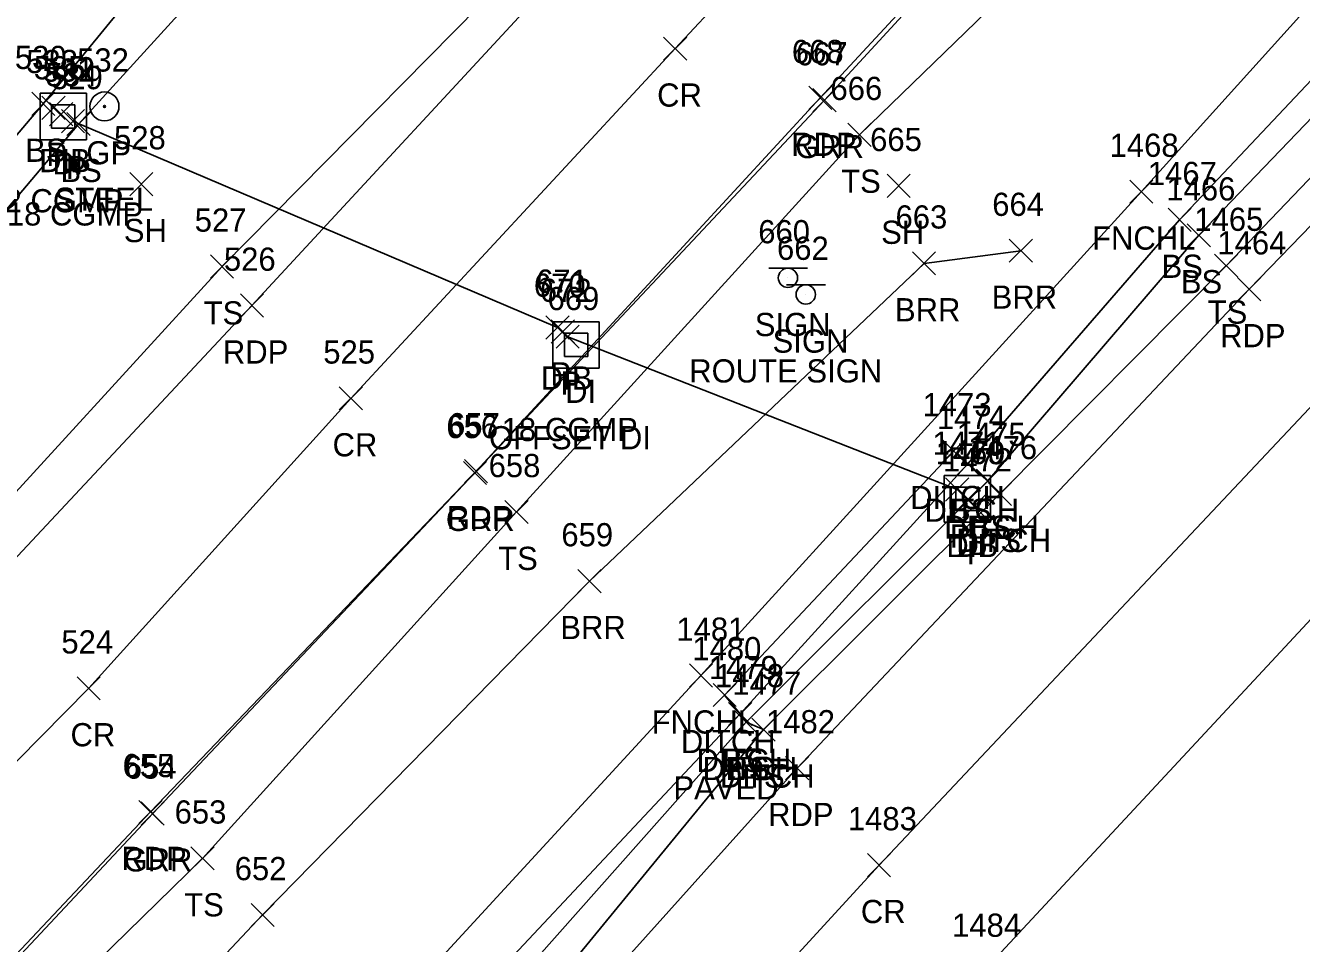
# Model space of a CAD drawing. Extents: x 1688195 to 1692013, y 424605 to 441234.
# Drawn here: x 1691404.7 to 1691514.7, y 438896.5 to 438975.6 of the extents above; entities that cross this region are included whole.
import ezdxf

# ---------------------------------------------------------------- set-up
doc = ezdxf.new("R2010")
doc.units = 0
for name, color, linetype in [('D_A', 7, 'Continuous'), ('D_C', 7, 'Continuous'), ('D_I', 7, 'Continuous'), ('D_TIC', 7, 'Continuous'), ('DCP', 7, 'Continuous'), ('DD', 7, 'Continuous'), ('DS', 7, 'Continuous'), ('L_A', 7, 'Continuous'), ('L_I', 7, 'Continuous'), ('L_TIC', 7, 'Continuous'), ('LABL', 7, 'Continuous'), ('LELB', 7, 'Continuous'), ('LFNC', 7, 'Continuous'), ('P_A', 7, 'Continuous'), ('P_I', 7, 'Continuous'), ('P_TIC', 7, 'Continuous'), ('PET', 7, 'Continuous'), ('PRC', 7, 'Continuous'), ('R_A', 7, 'Continuous'), ('R_C', 7, 'Continuous'), ('R_I', 7, 'Continuous'), ('R_TIC', 7, 'Continuous'), ('RGP', 7, 'Continuous'), ('RGR', 7, 'Continuous'), ('S_A', 7, 'Continuous'), ('S_C', 7, 'Continuous'), ('S_I', 7, 'Continuous'), ('SSGN', 7, 'Continuous')]:
    doc.layers.add(name, color=color, linetype=linetype)

msp = doc.modelspace()

# ---------------------------------------------------------------- linework, layer by layer
at = {"layer": 'D_TIC'}
for points in [[(1691406.08, 438967.48), (1691408.08, 438969.48)], [(1691408.08, 438967.48), (1691406.08, 438969.48)], [(1691406.74, 438966.94), (1691408.74, 438968.94)], [(1691408.74, 438966.94), (1691406.74, 438968.94)], [(1691407.75, 438966.34), (1691409.75, 438968.34)], [(1691409.75, 438966.34), (1691407.75, 438968.34)], [(1691449.54, 438948.55), (1691451.54, 438950.55)], [(1691451.54, 438948.55), (1691449.54, 438950.55)], [(1691449.99, 438948.2), (1691451.99, 438950.2)], [(1691451.99, 438948.2), (1691449.99, 438950.2)], [(1691450.42, 438947.76), (1691452.42, 438949.76)], [(1691452.42, 438947.76), (1691450.42, 438949.76)], [(1691483.71, 438937.9), (1691485.71, 438939.9)], [(1691485.71, 438937.9), (1691483.71, 438939.9)], [(1691483.71, 438937.9), (1691485.71, 438939.9)], [(1691485.71, 438937.9), (1691483.71, 438939.9)], [(1691484.94, 438936.8), (1691486.94, 438938.8)], [(1691486.94, 438936.8), (1691484.94, 438938.8)], [(1691484, 438934.58), (1691486, 438936.58)], [(1691486, 438934.58), (1691484, 438936.58)], [(1691486.66, 438935.34), (1691488.66, 438937.34)], [(1691488.66, 438935.34), (1691486.66, 438937.34)], [(1691484.96, 438933.76), (1691486.96, 438935.76)], [(1691486.96, 438933.76), (1691484.96, 438935.76)], [(1691487.69, 438934.2), (1691489.69, 438936.2)], [(1691489.69, 438934.2), (1691487.69, 438936.2)], [(1691485.47, 438933.15), (1691487.47, 438935.15)], [(1691487.47, 438933.15), (1691485.47, 438935.15)], [(1691463.95, 438916.87), (1691465.95, 438918.87)], [(1691465.95, 438916.87), (1691463.95, 438918.87)], [(1691463.95, 438916.87), (1691465.95, 438918.87)], [(1691465.95, 438916.87), (1691463.95, 438918.87)], [(1691465.29, 438915.24), (1691467.29, 438917.24)], [(1691467.29, 438915.24), (1691465.29, 438917.24)], [(1691465.81, 438914.54), (1691467.81, 438916.54)], [(1691467.81, 438914.54), (1691465.81, 438916.54)], [(1691467.3, 438913.89), (1691469.3, 438915.89)], [(1691469.3, 438913.89), (1691467.3, 438915.89)]]:
    msp.add_lwpolyline(points, dxfattribs=at)
at = {"layer": 'DCP'}
for points in [[(1691408.75, 438967.34), (1691450.54, 438949.55)], [(1691451.42, 438948.76), (1691485, 438935.58)]]:
    msp.add_lwpolyline(points, dxfattribs=at)
at = {"layer": 'DD'}
for points in [[(1691484.71, 438938.9), (1691485.94, 438937.8), (1691487.66, 438936.34), (1691488.69, 438935.2), (1691468.3, 438914.89), (1691466.81, 438915.54), (1691466.29, 438916.24), (1691464.95, 438917.87)], [(1691484.71, 438938.9), (1691464.95, 438917.87)]]:
    msp.add_lwpolyline(points, dxfattribs=at)
at = {"layer": 'DS'}
for p, q in [((1691405.91, 438969.74), (1691409.91, 438969.74)), ((1691405.91, 438965.74), (1691405.91, 438969.74)), ((1691409.91, 438969.74), (1691409.91, 438965.74)), ((1691406.91, 438966.74), (1691406.91, 438968.74)), ((1691406.91, 438968.74), (1691408.91, 438968.74)), ((1691408.91, 438968.74), (1691408.91, 438966.74)), ((1691407.91, 438967.74), (1691407.91, 438967.74)), ((1691407.91, 438967.74), (1691407.91, 438967.74)), ((1691408.91, 438966.74), (1691406.91, 438966.74)), ((1691409.91, 438965.74), (1691405.91, 438965.74)), ((1691450.14, 438950.05), (1691454.14, 438950.05)), ((1691450.14, 438946.05), (1691450.14, 438950.05)), ((1691454.14, 438950.05), (1691454.14, 438946.05)), ((1691451.14, 438947.05), (1691451.14, 438949.05)), ((1691451.14, 438949.05), (1691453.14, 438949.05)), ((1691453.14, 438949.05), (1691453.14, 438947.05)), ((1691452.14, 438948.05), (1691452.14, 438948.05)), ((1691452.14, 438948.05), (1691452.14, 438948.05)), ((1691453.14, 438947.05), (1691451.14, 438947.05)), ((1691454.14, 438946.05), (1691450.14, 438946.05)), ((1691483.88, 438936.78), (1691487.88, 438936.78)), ((1691483.88, 438932.78), (1691483.88, 438936.78)), ((1691487.88, 438936.78), (1691487.88, 438932.78)), ((1691484.88, 438933.78), (1691484.88, 438935.78)), ((1691484.88, 438935.78), (1691486.88, 438935.78)), ((1691486.88, 438935.78), (1691486.88, 438933.78)), ((1691485.89, 438934.78), (1691485.89, 438934.78)), ((1691485.89, 438934.78), (1691485.89, 438934.78)), ((1691486.88, 438933.78), (1691484.88, 438933.78)), ((1691487.88, 438932.78), (1691483.88, 438932.78))]:
    msp.add_line(p, q, dxfattribs=at)
at = {"layer": 'L_TIC'}
for points in [[(1691405.19, 438967.83), (1691407.19, 438969.83)], [(1691407.19, 438967.83), (1691405.19, 438969.83)], [(1691408.23, 438966.09), (1691410.23, 438968.09)], [(1691410.23, 438966.09), (1691408.23, 438968.09)], [(1691475.59, 438965.16), (1691477.59, 438967.16)], [(1691477.59, 438965.16), (1691475.59, 438967.16)], [(1691413.65, 438960.91), (1691415.65, 438962.91)], [(1691415.65, 438960.91), (1691413.65, 438962.91)], [(1691478.96, 438960.76), (1691480.96, 438962.76)], [(1691480.96, 438960.76), (1691478.96, 438962.76)], [(1691499.89, 438960.26), (1691501.89, 438962.26)], [(1691501.89, 438960.26), (1691499.89, 438962.26)], [(1691503.19, 438957.83), (1691505.19, 438959.83)], [(1691505.19, 438957.83), (1691503.19, 438959.83)], [(1691504.84, 438956.5), (1691506.84, 438958.5)], [(1691506.84, 438956.5), (1691504.84, 438958.5)], [(1691489.49, 438955.17), (1691491.49, 438957.17)], [(1691491.49, 438955.17), (1691489.49, 438957.17)], [(1691420.61, 438953.81), (1691422.61, 438955.81)], [(1691422.61, 438953.81), (1691420.61, 438955.81)], [(1691481.15, 438954.08), (1691483.15, 438956.08)], [(1691483.15, 438954.08), (1691481.15, 438956.08)], [(1691507.2, 438953.88), (1691509.2, 438955.88)], [(1691509.2, 438953.88), (1691507.2, 438955.88)], [(1691484.94, 438936.8), (1691486.94, 438938.8)], [(1691486.94, 438936.8), (1691484.94, 438938.8)], [(1691486.66, 438935.34), (1691488.66, 438937.34)], [(1691488.66, 438935.34), (1691486.66, 438937.34)], [(1691487.69, 438934.2), (1691489.69, 438936.2)], [(1691489.69, 438934.2), (1691487.69, 438936.2)], [(1691446.01, 438932.65), (1691448.01, 438934.65)], [(1691448.01, 438932.65), (1691446.01, 438934.65)], [(1691452.29, 438926.69), (1691454.29, 438928.69)], [(1691454.29, 438926.69), (1691452.29, 438928.69)], [(1691461.91, 438918.55), (1691463.91, 438920.55)], [(1691463.91, 438918.55), (1691461.91, 438920.55)], [(1691465.29, 438915.24), (1691467.29, 438917.24)], [(1691467.29, 438915.24), (1691465.29, 438917.24)], [(1691465.81, 438914.54), (1691467.81, 438916.54)], [(1691467.81, 438914.54), (1691465.81, 438916.54)], [(1691467.3, 438913.89), (1691469.3, 438915.89)], [(1691469.3, 438913.89), (1691467.3, 438915.89)], [(1691418.93, 438902.79), (1691420.93, 438904.79)], [(1691420.93, 438902.79), (1691418.93, 438904.79)], [(1691424.11, 438897.91), (1691426.11, 438899.91)], [(1691426.11, 438897.91), (1691424.11, 438899.91)]]:
    msp.add_lwpolyline(points, dxfattribs=at)
at = {"layer": 'LABL'}
msp.add_lwpolyline([(1691400.95, 438873.28), (1691425.11, 438898.91), (1691453.29, 438927.69), (1691482.15, 438955.08), (1691490.49, 438956.17)], dxfattribs=at)
at = {"layer": 'LELB'}
for points in [[(1691372.73, 438902.64), (1691398.57, 438929.63), (1691421.61, 438954.81), (1691450.5, 438984.08), (1691477.46, 439013.34), (1691508.26, 439046.52), (1691540.85, 439082.44), (1691568.31, 439110.72), (1691593.69, 439141.21), (1691622.93, 439171.73), (1691652.84, 439206.76), (1691674.71, 439229.19), (1691701.22, 439256.48), (1691710.89, 439279.75), (1691723.95, 439307.99), (1691712.17, 439332.07), (1691693.94, 439358.26), (1691684, 439373.02)], [(1691358.65, 438915.95), (1691383.88, 438942.54), (1691406.19, 438968.83), (1691432.09, 439000.43), (1691458.78, 439030.79), (1691488.91, 439063.66), (1691516.55, 439102.83), (1691546.52, 439127.21), (1691571.44, 439162.09), (1691585.36, 439179.75), (1691595.61, 439189.84), (1691598.8, 439192.56), (1691623.09, 439224.33), (1691645.87, 439250.99)], [(1691362.51, 438912.64), (1691386.93, 438940.67), (1691409.23, 438967.09), (1691436.47, 438996.99), (1691463, 439026.81), (1691492.43, 439060.22), (1691523.16, 439097.82), (1691549.35, 439125.66), (1691575.52, 439158.24), (1691588.61, 439176.65), (1691597.67, 439188.52), (1691599.59, 439192.01), (1691624.28, 439223.08), (1691646.72, 439249.94), (1691645.87, 439250.99)], [(1691809.05, 439198.7), (1691810.07, 439220.42), (1691810.47, 439227.71), (1691810.04, 439233.75), (1691820.98, 439231.16), (1691837.25, 439226.41), (1691844.55, 439222.68), (1691860.67, 439213.28), (1691879.41, 439197.19), (1691884.86, 439187.77), (1691888.44, 439178.13), (1691882, 439154.55), (1691849.25, 439142.61), (1691815.33, 439128.47), (1691761.5, 439106.68), (1691722.87, 439092.03), (1691697.52, 439087.73), (1691657.95, 439070.39), (1691613.62, 439049.58), (1691576.98, 439020.14), (1691544.83, 438993.15), (1691508.2, 438954.88), (1691488.69, 438935.2)], [(1691867.08, 439165.21), (1691844.95, 439160.27), (1691798.84, 439152.11), (1691745.51, 439147.11), (1691728.71, 439142.4), (1691709.09, 439133.88), (1691683, 439117.2), (1691643.28, 439091.08), (1691604.89, 439061.29), (1691572.53, 439026.72), (1691542.38, 438995.55), (1691505.84, 438957.5), (1691487.66, 438936.34), (1691466.81, 438915.54), (1691436.02, 438880.86), (1691415.55, 438858.76)], [(1691604.89, 439061.29), (1691570.2, 439029.58), (1691540.68, 438997.55), (1691504.19, 438958.83), (1691485.94, 438937.8), (1691466.29, 438916.24), (1691434.59, 438882.45), (1691414.01, 438860.1)], [(1691395.27, 438879.71), (1691419.93, 438903.79), (1691447.01, 438933.65), (1691476.59, 438966.16), (1691497.62, 438986.55)], [(1691468.3, 438914.89), (1691438.62, 438878.72), (1691416.93, 438857.19)]]:
    msp.add_lwpolyline(points, dxfattribs=at)
at = {"layer": 'LFNC'}
msp.add_lwpolyline([(1691844.63, 439219.19), (1691827.3, 439208.18), (1691808.98, 439197.07), (1691805.18, 439194.78), (1691802.65, 439193.15), (1691780.93, 439179.95), (1691740.49, 439155.55), (1691707.63, 439134.9), (1691682.09, 439120.04), (1691638.96, 439093.47), (1691599.84, 439067.34), (1691566.38, 439033.38), (1691536.95, 439001.22), (1691500.89, 438961.26), (1691462.91, 438919.55), (1691429.39, 438883.14), (1691411.26, 438863.12)], dxfattribs=at)
at = {"layer": 'P_TIC'}
for points in [[(1691459.69, 438972.59), (1691461.69, 438974.59)], [(1691461.69, 438972.59), (1691459.69, 438974.59)], [(1691472.2, 438968.34), (1691474.2, 438970.34)], [(1691474.2, 438968.34), (1691472.2, 438970.34)], [(1691509.19, 438951.85), (1691511.19, 438953.85)], [(1691511.19, 438951.85), (1691509.19, 438953.85)], [(1691423.19, 438950.44), (1691425.19, 438952.44)], [(1691425.19, 438950.44), (1691423.19, 438952.44)], [(1691431.71, 438942.44), (1691433.71, 438944.44)], [(1691433.71, 438942.44), (1691431.71, 438944.44)], [(1691442.51, 438936.17), (1691444.51, 438938.17)], [(1691444.51, 438936.17), (1691442.51, 438938.17)], [(1691409.11, 438917.45), (1691411.11, 438919.45)], [(1691411.11, 438917.45), (1691409.11, 438919.45)], [(1691470.21, 438910.57), (1691472.21, 438912.57)], [(1691472.21, 438910.57), (1691470.21, 438912.57)], [(1691414.43, 438906.79), (1691416.43, 438908.79)], [(1691416.43, 438906.79), (1691414.43, 438908.79)], [(1691477.27, 438902.21), (1691479.27, 438904.21)], [(1691479.27, 438902.21), (1691477.27, 438904.21)]]:
    msp.add_lwpolyline(points, dxfattribs=at)
at = {"layer": 'PET'}
for points in [[(1691375.46, 438899.9), (1691401.5, 438927.23), (1691424.19, 438951.44), (1691479.53, 439011.25), (1691510.32, 439044.28), (1691543.27, 439079.53), (1691570.24, 439108.89), (1691596.97, 439137.86), (1691630.02, 439173.34), (1691657.32, 439202.46), (1691678.85, 439225.99), (1691705.09, 439253.29), (1691720.65, 439270.18), (1691741.75, 439292.31), (1691750.04, 439301.33), (1691750.82, 439305.81), (1691750.97, 439309.53)], [(1691392.15, 438883.12), (1691415.43, 438907.79), (1691443.51, 438937.17), (1691473.2, 438969.34), (1691494.19, 438991.98), (1691527.98, 439028.02), (1691561.01, 439063.43)], [(1691620.88, 439044.07), (1691602.22, 439033.1), (1691579.03, 439017.01), (1691566.59, 439007.7), (1691551.73, 438994.67), (1691535.43, 438978.91), (1691510.19, 438952.85), (1691471.21, 438911.57), (1691440.28, 438877.12), (1691419.08, 438855.12)], [(1691672.86, 439042.9), (1691649.54, 439032.89), (1691634.02, 439024.76), (1691613.34, 439012.41), (1691591.31, 438997.78), (1691582.05, 438990.56), (1691567.39, 438977.9), (1691551.1, 438962.07), (1691527.82, 438937.62), (1691487.26, 438894.03), (1691457.21, 438860.6), (1691436.01, 438838.17)]]:
    msp.add_lwpolyline(points, dxfattribs=at)
at = {"layer": 'PRC'}
for points in [[(1691383.45, 438891.46), (1691410.11, 438918.45), (1691432.71, 438943.44), (1691460.69, 438973.59), (1691487.77, 439002.58), (1691519.39, 439036.11), (1691551.83, 439070.88), (1691579.21, 439100.29), (1691605.82, 439129.37), (1691637.88, 439164.38), (1691665.6, 439193.96), (1691687.96, 439216.92), (1691714.01, 439245.27), (1691730.35, 439261.96), (1691750.53, 439284.62), (1691763.38, 439297.71)], [(1691888.13, 439193.66), (1691921.53, 439164.99), (1691933.61, 439155.1), (1691905.33, 439143.8), (1691864.7, 439127.18), (1691822.78, 439112.3), (1691787.26, 439099.58), (1691756.92, 439088.3), (1691729.19, 439077.85), (1691704.03, 439068.3), (1691667.7, 439053.5), (1691645.71, 439043.49), (1691628.46, 439034.88), (1691608.73, 439022.92), (1691585.22, 439006.39), (1691574.92, 438998.75), (1691559.84, 438985.93), (1691543.5, 438970.76), (1691518.61, 438946.02), (1691478.27, 438903.21), (1691447.81, 438870), (1691426.94, 438847.45)]]:
    msp.add_lwpolyline(points, dxfattribs=at)
at = {"layer": 'R_TIC'}
for points in [[(1691472.56, 438968.15), (1691474.56, 438970.15)], [(1691474.56, 438968.15), (1691472.56, 438970.15)], [(1691442.42, 438936.01), (1691444.42, 438938.01)], [(1691444.42, 438936.01), (1691442.42, 438938.01)], [(1691414.63, 438906.66), (1691416.63, 438908.66)], [(1691416.63, 438906.66), (1691414.63, 438908.66)]]:
    msp.add_lwpolyline(points, dxfattribs=at)
at = {"layer": 'RGP'}
msp.add_line((1691411.47, 438968.61), (1691411.47, 438968.61), dxfattribs=at)
for radius in [1.25, 0.0833]:
    msp.add_circle((1691411.47, 438968.61), radius, dxfattribs=at)
at = {"layer": 'RGR'}
msp.add_lwpolyline([(1691392.43, 438882.91), (1691415.63, 438907.66), (1691443.42, 438937.01), (1691473.56, 438969.15), (1691494.4, 438991.79), (1691528.19, 439027.86), (1691561.17, 439063.3), (1691590.77, 439094.95), (1691620.16, 439126.42), (1691638.64, 439146.14), (1691654.09, 439162.7)], dxfattribs=at)
at = {"layer": 'SSGN'}
for p, q in [((1691468.77, 438954.67), (1691472.1, 438954.67)), ((1691470.3, 438953.23), (1691473.64, 438953.23)), ((1691470.41, 438953.83), (1691470.41, 438953.83)), ((1691471.95, 438952.4), (1691471.95, 438952.4))]:
    msp.add_line(p, q, dxfattribs=at)
for centre in [(1691470.41, 438953.83), (1691471.95, 438952.4)]:
    msp.add_circle(centre, 0.833, dxfattribs=at)

# ---------------------------------------------------------------- texts
at = {"layer": 'D_A'}
for s, p in [('DIB', (1691405.84, 438962.94)), ('P', (1691406.46, 438963.48)), ('DI', (1691406.97, 438962.74)), ('P', (1691408.13, 438962.34)), ('DIB', (1691449.1, 438944.2)), ('P', (1691449.92, 438944.55)), ('P', (1691450.8, 438943.76)), ('DI', (1691451.2, 438943.05)), ('DITCH', (1691480.95, 438933.9)), ('DITCH', (1691480.95, 438933.9)), ('DITCH', (1691482.18, 438932.8)), ('DITCH', (1691483.89, 438931.34)), ('P', (1691484.38, 438930.58)), ('DITCH', (1691484.93, 438930.2)), ('DIB', (1691484.07, 438929.76)), ('DI', (1691484.95, 438929.78)), ('P', (1691485.85, 438929.15)), ('DITCH', (1691461.18, 438912.87)), ('DITCH', (1691461.18, 438912.87)), ('DITCH', (1691462.53, 438911.24)), ('DITCH', (1691463.05, 438910.54)), ('DITCH', (1691464.54, 438909.89))]:
    msp.add_text(s, height=2, dxfattribs=at).set_placement(p)
at = {"layer": 'D_C'}
for s, p in [('12 CGMP', (1691401.37, 438959.48)), ('18 CGMP', (1691403.05, 438958.34)), ('OFFSET DI', (1691444.63, 438939.05)), ('18 CGMP', (1691445.72, 438939.76)), ('PAVED', (1691460.53, 438908.87)), ('PAVED', (1691460.53, 438908.87))]:
    msp.add_text(s, height=2, dxfattribs=at).set_placement(p)
at = {"layer": 'D_I'}
for s, p in [('533', (1691404.72, 438971.48)), ('535', (1691405.37, 438970.94)), ('531', (1691406.12, 438970.74)), ('534', (1691406.39, 438970.34)), ('670', (1691448.5, 438952.2)), ('671', (1691448.7, 438952.55)), ('672', (1691449.02, 438951.76)), ('669', (1691449.68, 438951.05)), ('1473', (1691482.02, 438941.9)), ('1473', (1691482.02, 438941.9)), ('1474', (1691483.25, 438940.8)), ('1475', (1691484.96, 438939.34)), ('1471', (1691482.88, 438938.58)), ('1469', (1691483.14, 438937.78)), ('1470', (1691483.19, 438937.76)), ('1476', (1691485.95, 438938.2)), ('1472', (1691483.78, 438937.15)), ('1480', (1691462.17, 438920.87)), ('1480', (1691462.17, 438920.87)), ('1479', (1691463.59, 438919.24)), ('1478', (1691464.12, 438918.54)), ('1477', (1691465.61, 438917.89))]:
    msp.add_text(s, height=2, dxfattribs=at).set_placement(p)
at = {"layer": 'L_A'}
for s, p in [('BS', (1691404.63, 438963.83)), ('BS', (1691407.67, 438962.09)), ('TS', (1691475, 438961.16)), ('SH', (1691413.14, 438956.91)), ('SH', (1691478.45, 438956.76)), ('FNCHL', (1691496.64, 438956.26)), ('BS', (1691502.63, 438953.83)), ('BS', (1691504.29, 438952.5)), ('BRR', (1691487.98, 438951.17)), ('TS', (1691420.02, 438949.81)), ('BRR', (1691479.64, 438950.08)), ('TS', (1691506.61, 438949.88)), ('BS', (1691484.38, 438932.8)), ('BS', (1691486.1, 438931.34)), ('TS', (1691487.1, 438930.2)), ('TS', (1691445.42, 438928.65)), ('BRR', (1691450.78, 438922.69)), ('FNCHL', (1691458.66, 438914.55)), ('BS', (1691464.74, 438911.24)), ('BS', (1691465.25, 438910.54)), ('TS', (1691466.71, 438909.89)), ('TS', (1691418.34, 438898.79))]:
    msp.add_text(s, height=2, dxfattribs=at).set_placement(p)
at = {"layer": 'L_I'}
for s, p in [('530', (1691403.74, 438971.83)), ('529', (1691406.86, 438970.09)), ('666', (1691474.08, 438969.16)), ('528', (1691412.29, 438964.91)), ('665', (1691477.5, 438964.76)), ('1468', (1691498.15, 438964.26)), ('1467', (1691501.45, 438961.83)), ('1466', (1691503.05, 438960.5)), ('664', (1691488.03, 438959.17)), ('527', (1691419.25, 438957.81)), ('663', (1691479.69, 438958.08)), ('1465', (1691505.46, 438957.88)), ('1474', (1691483.25, 438940.8)), ('1475', (1691484.96, 438939.34)), ('1476', (1691485.95, 438938.2)), ('658', (1691444.6, 438936.65)), ('659', (1691450.87, 438930.69)), ('1481', (1691460.79, 438922.55)), ('1479', (1691463.59, 438919.24)), ('1478', (1691464.12, 438918.54)), ('1477', (1691465.61, 438917.89)), ('653', (1691417.52, 438906.79)), ('652', (1691422.7, 438901.91))]:
    msp.add_text(s, height=2, dxfattribs=at).set_placement(p)
at = {"layer": 'P_A'}
for s, p in [('CR', (1691459.13, 438968.59)), ('RDP', (1691470.69, 438964.34)), ('RDP', (1691507.68, 438947.85)), ('RDP', (1691421.68, 438946.44)), ('CR', (1691431.14, 438938.44)), ('RDP', (1691441, 438932.17)), ('CR', (1691408.54, 438913.45)), ('RDP', (1691468.7, 438906.57)), ('RDP', (1691412.92, 438902.79)), ('CR', (1691476.7, 438898.21))]:
    msp.add_text(s, height=2, dxfattribs=at).set_placement(p)
at = {"layer": 'P_I'}
for s, p in [('668', (1691470.75, 438972.34)), ('1464', (1691507.45, 438955.85)), ('526', (1691421.77, 438954.44)), ('525', (1691430.34, 438946.44)), ('657', (1691441.1, 438940.17)), ('524', (1691407.75, 438921.45)), ('1482', (1691468.52, 438914.57)), ('655', (1691413.03, 438910.79)), ('1483', (1691475.58, 438906.21)), ('1484', (1691484.57, 438897.03))]:
    msp.add_text(s, height=2, dxfattribs=at).set_placement(p)
at = {"layer": 'R_A'}
for s, p in [('GRR', (1691471.04, 438964.15)), ('GP', (1691409.9, 438963.61)), ('GRR', (1691440.91, 438932.01)), ('GRR', (1691413.11, 438902.66))]:
    msp.add_text(s, height=2, dxfattribs=at).set_placement(p)
at = {"layer": 'R_C'}
msp.add_text('STEEL', height=2, dxfattribs=at).set_placement((1691407.18, 438959.61))
at = {"layer": 'R_I'}
for s, p in [('667', (1691471.1, 438972.15)), ('532', (1691409.11, 438971.61)), ('656', (1691440.95, 438940.01)), ('654', (1691413.22, 438910.66))]:
    msp.add_text(s, height=2, dxfattribs=at).set_placement(p)
at = {"layer": 'S_A'}
for p in [(1691467.55, 438948.81), (1691469.09, 438947.38)]:
    msp.add_text('SIGN', height=2, dxfattribs=at).set_placement(p)
at = {"layer": 'S_C'}
msp.add_text('ROUTE SIGN', height=2, dxfattribs=at).set_placement((1691461.9, 438944.81))
at = {"layer": 'S_I'}
for s, p in [('660', (1691467.85, 438956.81)), ('662', (1691469.47, 438955.38))]:
    msp.add_text(s, height=2, dxfattribs=at).set_placement(p)

doc.saveas('drawing.dxf')
